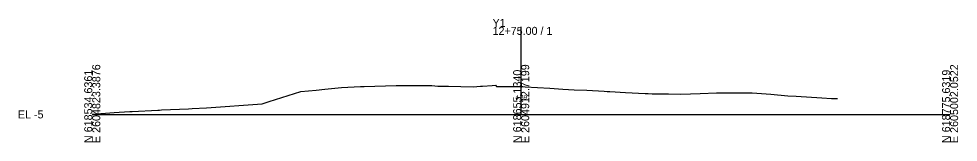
# Model space of a CAD drawing. Extents: x -26 to 1603, y -10 to 2541.
# Drawn here: x 1274.3 to 1602.8, y -9.7 to 33.4 of the extents above; entities that cross this region are included whole.
import ezdxf

# ---------------------------------------------------------------- set-up
doc = ezdxf.new("R2010")
doc.units = 0
for name, color, linetype in [('Exist Cross Section Cell', 7, 'Continuous'), ('Exist XS Center Line Elevation Label', 7, 'Continuous'), ('Exist XS Ground Line', 7, 'Continuous')]:
    doc.layers.add(name, color=color, linetype=linetype)

msp = doc.modelspace()

# ---------------------------------------------------------------- linework, layer by layer
at = {"layer": 'Exist Cross Section Cell'}
for p, q in [((1450, 0), (1450, 30.55)), ((1300, 0), (1450, 0)), ((1450, 0), (1600, 0))]:
    msp.add_line(p, q, dxfattribs=at)
at = {"layer": 'Exist XS Ground Line'}
msp.add_lwpolyline([(1300, 0.12), (1307.63, 0.66), (1309.44, 0.77), (1313.09, 0.97), (1313.95, 1.01), (1322.99, 1.47), (1323.53, 1.52), (1324.18, 1.54), (1333.64, 1.92), (1334.97, 2), (1339.9, 2.3), (1359.41, 3.72), (1361.82, 4.46), (1372.9, 7.96), (1378.27, 8.46), (1381.37, 8.81), (1387.2, 9.37), (1393.82, 9.68), (1395.06, 9.75), (1406.26, 10.12), (1411.85, 10.13), (1415.79, 10.11), (1418.74, 10.05), (1420.9, 9.84), (1424.62, 9.8), (1433.17, 9.58), (1435.79, 9.81), (1436.48, 9.87), (1439.87, 10.13), (1441.06, 10.18), (1441.36, 9.78), (1450, 9.69), (1450.63, 9.68), (1451.43, 9.64), (1460.07, 9.16), (1464.56, 8.81), (1468.51, 8.54), (1472.98, 8.41), (1479.02, 8.1), (1480.13, 8.01), (1480.95, 7.98), (1486.51, 7.69), (1493.4, 7.25), (1494.43, 7.27), (1495.81, 7.2), (1501.57, 7.13), (1505.85, 7.01), (1512.6, 7.32), (1518.3, 7.58), (1523.02, 7.57), (1529.39, 7.56), (1530.75, 7.54), (1537.32, 7.02), (1543.2, 6.5), (1546.18, 6.32), (1555.2, 5.75), (1558.49, 5.54), (1559.15, 5.54), (1559.98, 5.54), (1560.64, 5.54)], dxfattribs=at)

# ---------------------------------------------------------------- texts
at = {"layer": 'Exist Cross Section Cell'}
for s, p in [('Y1', (1440, 30.55)), ('12+75.00 / 1', (1440, 27.75)), ('EL -5', (1274, -1.4))]:
    msp.add_text(s, height=2.8, dxfattribs=at).set_placement(p)
for s, p in [('E 2604823.3876', (1302.8, -10)), ('E 2604912.7199', (1452.8, -10)), ('E 2605002.0522', (1602.8, -10)), ('N 618534.6361', (1300, -10)), ('N 618655.1340', (1450, -10)), ('N 618775.6319', (1600, -10))]:
    msp.add_text(s, height=2.8, rotation=90, dxfattribs=at).set_placement(p)
at = {"layer": 'Exist XS Center Line Elevation Label'}
msp.add_text('4.69', height=1.5, dxfattribs=at).set_placement((1447.99, 5.19))

doc.saveas('drawing.dxf')
